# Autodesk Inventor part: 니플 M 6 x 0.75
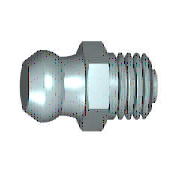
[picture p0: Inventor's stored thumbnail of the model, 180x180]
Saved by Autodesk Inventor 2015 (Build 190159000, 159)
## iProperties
IsCustomPart: 1
Created: 2012-02
Part Number: 니플 M 6 x 0.75
Material: 강철, 연강
Description: 윤활 니플, 원추 유형 A
Document SubType Name: Modeling
Standard: JIS B 1575
Designer: mduedu
Standards Organization: JIS
Language: ko-KR
Size Designation: MT 6 x 0.75
Categories: <MemberInstance><Categories><Category DisplayName="기타 부품" InternalName="5aa15e00-363f-49f2-933f-16f664388e3f" Mnemonic="OTHER"><Category DisplayName="그리스 부속품" I
Density: 1 g/cm^3
Appearance: 강철
Author: mduedu
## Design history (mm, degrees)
sketch "스케치1"
  geometry: L1 (-8.8, 0)-(-8.8, 2.4); L2 (-8.8, 2.4)-(-7.335, 3.202); L3 (-8.8, 0)-(4.7, 0); L4 (4.7, 0)-(4.7, 1.5); L5 (4.7, 1.5)-(4, 1.5); L6 (4, 1.5)-(4, 3); L7 (4, 3)-(0, 3); L8 (-11.5, 0)-(7.4, 0) reference; L9 (0, -1.733)-(0, 10.398) reference; L10 (-3, 3.5)-(0, 3.5); L11 (0, 3.5)-(0, 3); A1 r 3.3 centre (-6.535, 0) between (-4.789, 2.8) and (-7.335, 3.202); A2 r 6 centre (-6.053, 8.665) between (-4.789, 2.8) and (-3, 3.5)
  constraints: 18 end point, 5 perpendicular, 4 point on circle, 2 centre point, 2 parallel, 2 point on line, 1 collinear, 1 vertical
  dimensions: "d0" = 13.5 distance between parallel lines of L1 L4 (= GL); "d1" = 5.6 diameter of A1.start L3 (= KGB2); "d2" = 0.7 distance between parallel lines of L4 L6 (= PHH); "d3" = 3 diameter of L5 L3 (= 0.5 x NND); "d4" = 6 diameter of L7 L3 (= NND); "d5" = 6.6 dimension on A1 L3 (= KR); "d6" = 4.8 diameter of L1.end L3 (= KGB1); "d7" = 6 radius of A2 (= RBN); "d11" = 7 diameter of L10.start L3 (= SW); "d14" = 3 distance of L10.start L10.end (= KOH); "d15" = 4 distance between parallel lines of L6 L11 (= NLG); "d61" = 7.33505 distance from line of L9 L2.end (computed from KGB1, KR, PHH, GL, NLG, VERS); "d62" = 6.53505 distance from line of L9 A1.centre (computed from NLG, GL, PHH, KR, KGB1)
revolve "본체" sketch "스케치1" stored, may be unused: angle "d25" = 90 deg
sketch "스케치2"
  geometry: L1 (2.021, 3.5)-(4.041, 0); L2 (4.041, 0)-(2.021, -3.5); L3 (2.021, -3.5)-(-2.021, -3.5); L4 (-2.021, -3.5)-(-4.041, 0); L5 (-4.041, 0)-(-2.021, 3.5); L6 (-2.021, 3.5)-(2.021, 3.5); C1 r 3.5 at (0, 0) reference; 1 further point
  constraints: 12 end point, 1 coincident, 1 horizontal, 1 tangent, 11 other
extrude "머리" join sketch "스케치2" distance "d17" = 3 (= KOH); taper "d18" = 0 deg
sketch "스케치3"
  geometry: L1 (2.687, 4.041)-(3, 4.041); L2 (3, 4.041)-(3, 3.5); L3 (3, 3.5)-(2.687, 4.041); L4 (0.313, 4.041)-(0, 4.041); L5 (0, 4.041)-(0, 3.5); L6 (0, 3.5)-(0.313, 4.041); L7 (3.6, 0)-(-0.6, 0) reference; L8 (0, 4.041)-(0, 2.021) reference; L9 (0, 4.041)-(3, 4.041) reference; L10 (3, 3.031)-(3, 4.041) reference
  constraints: 12 end point, 4 collinear, 3 perpendicular, 1 horizontal
  dimensions: "d19" = 3.5 distance from line of L5.end L7 (= 0.5 x SW); "d20" = 3.5 distance from line of L2.end L7 (= 0.5 x SW); "d21" = 30 deg angle of L6 L5; "d22" = 30 deg angle of L2 L3
revolve "모따기1" sketch "스케치3" stored, may be unused: angle "d56" = 90 deg
body "Solid1"
fillet "모깎기1" dims "d8" = 0.2 (= RR)
feature "스레드1" dims "d9" = 3.53991 (= NLG - GAL), "d10" = 0
chamfer "모따기2" distance "d23" = 0.46009 (= -0.5 x GD1 + 0.5 x NND); stored, may be unused: angle "d24" = 45 deg, second distance "d59" = 0.46009 (= -0.5 x GD1 + 0.5 x NND)
other parameters: "NLG" = 4 [user parameter; used in 4 equation terms], "GL" = 13.5 [user parameter; used in 3 equation terms], "NND" = 6 [user parameter; used in 4 equation terms], "KGB1" = 4.8 [user parameter; used in 3 equation terms], "KGB2" = 5.6 [user parameter; used in 1 equation term], "VERS" = 0.8 [user parameter; used in 1 equation term], "KR" = 6.6 [user parameter; used in 3 equation terms], "RBN" = 6 [user parameter; used in 1 equation term], "SW" = 7 [user parameter; used in 3 equation terms], "KOH" = 3 [user parameter; used in 2 equation terms], "GAL" = 0.46009 (= 0.61345 x PTC) [user parameter; used in 1 equation term], "FAWI" = 45 deg [user parameter], "PHH" = 0.7 [user parameter; used in 3 equation terms], "GD1" = 5.07983 (= THREADDIA - 1.2269 x PTC) [user parameter; used in 2 equation terms], "RR" = 0.2 [user parameter; used in 1 equation term], "d12" = 0, "d13" = 0, "GUL" = 0.46009 (= 0.61345 x PTC) [user parameter], "TPU" = 13.33333 (computed from PTC) [user parameter], "DULO" = 1.5 [user parameter], "PTC" = 0.75 [user parameter; used in 4 equation terms], "GEL" = 4 [user parameter], "THREADDIA" = 6 [user parameter; used in 1 equation term], "TOA" = 30 deg [user parameter]
